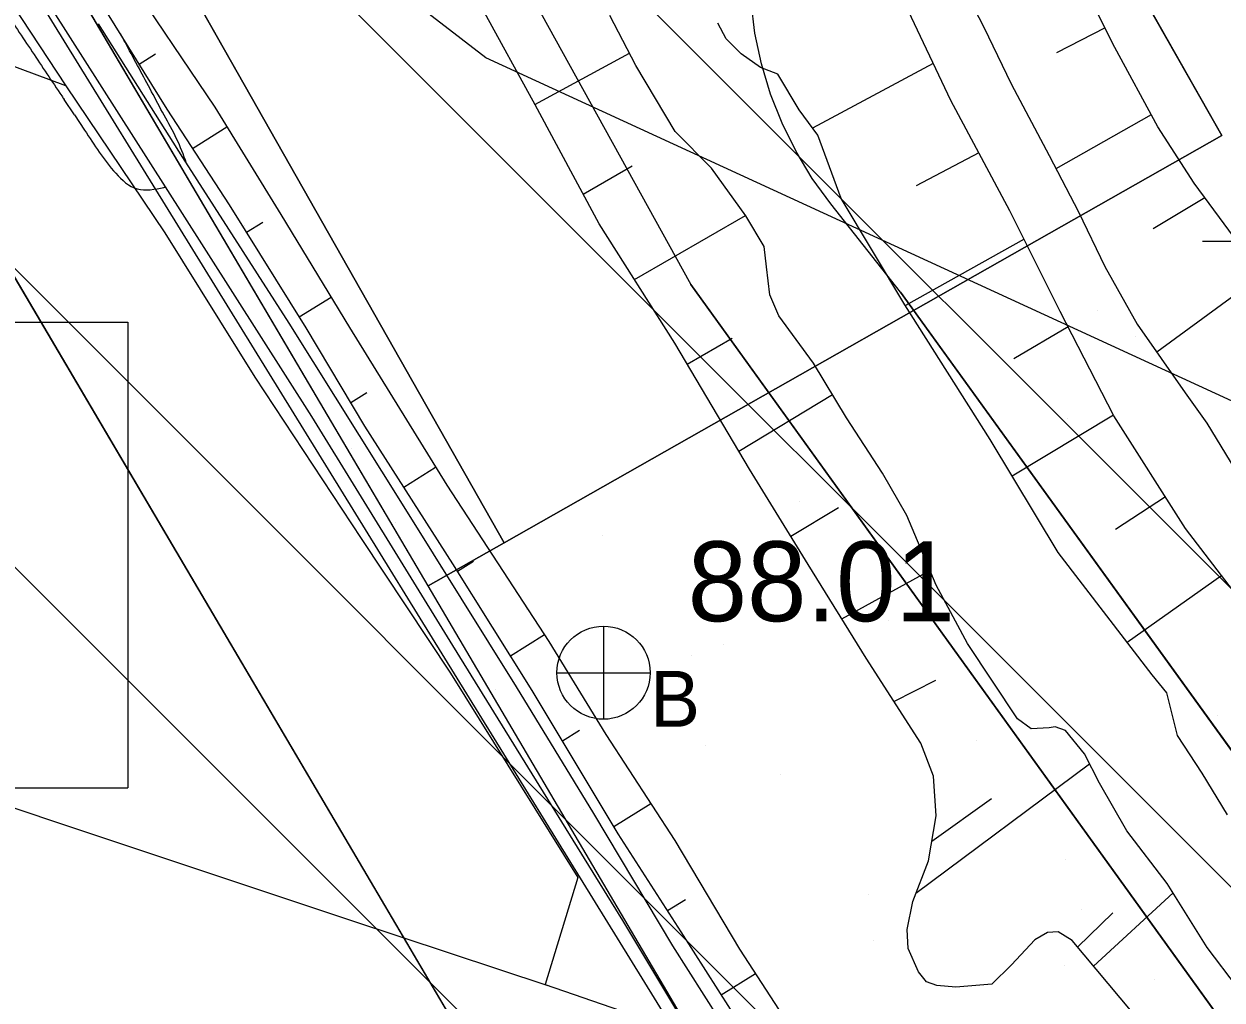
# Model space of a CAD drawing. Extents: x 417995 to 421451, y 4454518 to 4458015.
# Drawn here: x 420893.9 to 420983.9, y 4456249.9 to 4456323.2 of the extents above; entities that cross this region are included whole.
import ezdxf

# ---------------------------------------------------------------- set-up
doc = ezdxf.new("R2010")
doc.units = 0
for name, color, linetype in [('ADAKENARI', 7, 'Continuous'), ('Default', 7, 'Continuous'), ('Egri_1m', 7, 'Continuous'), ('Hid_Dere_Sulu_Yat_Gen', 7, 'Continuous'), ('PL_AYA_PARK_DINLENME', 7, 'Continuous'), ('PL_TA_K_DERE', 7, 'Continuous'), ('PL_TA_K_OTOPARK', 7, 'Continuous'), ('S_Rogar_Kapagi_Buski', 7, 'Continuous'), ('SEMBOL_FAT', 7, 'Continuous'), ('Sev_Sevalti', 7, 'Continuous'), ('Sev_Sevustu', 7, 'Continuous'), ('Sev_Tarama', 7, 'Continuous'), ('Sinir_itirazli_Mulkiyet', 7, 'Continuous'), ('Sinir_Tel_bir_taraf', 7, 'Continuous'), ('SN_TASKIN', 7, 'Continuous'), ('SN_TR_SIVILASMA', 7, 'Continuous'), ('SN_TR_TASKIN', 7, 'Continuous'), ('TR_PARKALANI', 7, 'Continuous'), ('TRFAT_PARKALANI', 7, 'Continuous'), ('Y_Kot_Noktasi', 7, 'Continuous'), ('Yol_Toprak_Duz', 7, 'Continuous'), ('Yol_Toprak_Kesik', 7, 'Continuous')]:
    doc.layers.add(name, color=color, linetype=linetype)

# ---------------------------------------------------------------- blocks, each defined once
blk = doc.blocks.new('POINT_DISPLAY')
at = {"layer": 'Default'}
blk.add_line((0, 0), (0, 0), dxfattribs=at)

msp = doc.modelspace()

# ---------------------------------------------------------------- linework, layer by layer
at = {"layer": 'ADAKENARI'}
for p, q in [((420983.888, 4456314.841), (420905.427, 4456453.119)), ((420924.233, 4456280.992), (420830.138, 4456440.665)), ((420852.304, 4456421.109), (420929.964, 4456284.244)), ((420866.39, 4456349.603), (420927.08, 4456246.617)), ((420929.964, 4456284.244), (420983.888, 4456314.841)), ((421053.63, 4456151.536), (420943.982, 4456303.649)), ((420959.726, 4456303.082), (421038.213, 4456194.409)), ((420924.233, 4456280.992), (420929.964, 4456284.244)), ((420960.939, 4456218.704), (420924.233, 4456280.992))]:
    msp.add_line(p, q, dxfattribs=at)
at = {"layer": 'Egri_1m'}
for q in [(420896.883, 4456317.563), (420898.428, 4456315.254)]:
    msp.add_line((420897.657, 4456316.409), q, dxfattribs=at)
for points in [[(420869.103, 4456359.489), (420870.183, 4456357.805), (420871.263, 4456356.121), (420872.342, 4456354.438), (420873.421, 4456352.754), (420874.5, 4456351.07), (420875.616, 4456349.41), (420876.793, 4456347.793), (420877.987, 4456346.189), (420879.182, 4456344.585), (420880.35, 4456342.961), (420881.455, 4456341.294), (420882.546, 4456339.618), (420883.636, 4456337.941), (420884.725, 4456336.264), (420885.81, 4456334.583), (420886.894, 4456332.903), (420887.978, 4456331.222), (420889.053, 4456329.536), (420890.129, 4456327.849), (420891.21, 4456326.167), (420892.294, 4456324.486), (420893.38, 4456322.807), (420894.487, 4456321.141), (420895.597, 4456319.477), (420896.712, 4456317.817), (420896.883, 4456317.563)], [(420906.094, 4456312.755), (420905.344, 4456314.609), (420904.402, 4456316.373), (420903.458, 4456318.137), (420902.514, 4456319.9), (420901.57, 4456321.663), (420901.147, 4456322.453)], [(420898.428, 4456315.254), (420899.533, 4456313.587), (420900.762, 4456312.009), (420902.379, 4456310.831), (420904.375, 4456310.944), (420904.484, 4456310.966)]]:
    msp.add_spline(points, degree=3, dxfattribs=at)
at = {"layer": 'Hid_Dere_Sulu_Yat_Gen'}
for points in [[(420985.062, 4456250.81), (420982.785, 4456253.81), (420979.767, 4456258.638), (420976.75, 4456262.595), (420974.698, 4456266.18), (420973.568, 4456268.371), (420972.138, 4456270.12), (420971.368, 4456270.413), (420970.898, 4456270.332), (420969.556, 4456270.251), (420968.519, 4456271.015), (420964.769, 4456276.679), (420962.421, 4456281.063), (420960.203, 4456286.282), (420958.387, 4456289.473), (420955.677, 4456293.622), (420953.195, 4456297.746), (420950.588, 4456301.305), (420949.93, 4456302.881), (420949.671, 4456304.974), (420949.481, 4456306.5), (420948.123, 4456308.814), (420945.548, 4456312.395), (420942.811, 4456315.14), (420939.86, 4456320.108), (420937.908, 4456323.855)], [(420984.314, 4456263.798), (420982.419, 4456266.915), (420980.554, 4456269.748), (420979.762, 4456272.97), (420978.644, 4456274.313), (420971.575, 4456283.501), (420966.485, 4456291.995), (420960.072, 4456302.133), (420955.291, 4456310.117), (420953.517, 4456314.873), (420952.132, 4456316.785), (420950.527, 4456319.462), (420949.214, 4456319.969), (420947.753, 4456320.979), (420946.632, 4456322.104), (420946.024, 4456323.298)]]:
    msp.add_lwpolyline(points, dxfattribs=at)
at = {"layer": 'PL_AYA_PARK_DINLENME'}
msp.add_lwpolyline([(420398.451, 4456770.435), (420341.542, 4456780.97), (420343.747, 4456814.103), (420500.975, 4456742.521), (420572.513, 4456705.355), (420639.693, 4456661.01), (420701.864, 4456609.89), (420758.351, 4456552.552), (420808.535, 4456489.624), (420852.304, 4456421.109), (420929.964, 4456284.244), (420924.233, 4456280.992), (420830.138, 4456440.665), (420780.571, 4456521.605), (420657.58, 4456639.752), (420530.801, 4456712.428), (420483.239, 4456735.932), (420462.904, 4456746.949), (420444.362, 4456753.772)], close=True, dxfattribs=at)
for points in [[(420806.621, 4456538.493), (420839.115, 4456497.136), (420881.948, 4456423.286), (420925.715, 4456349.165), (420926.198, 4456348.307), (420926.647, 4456347.431), (420927.06, 4456346.537), (420927.436, 4456345.627), (420927.776, 4456344.702), (420928.078, 4456343.765), (420928.342, 4456342.816), (420928.568, 4456341.858), (420932.166, 4456325.065), (420943.982, 4456303.649), (421053.63, 4456151.536)], [(421036.852, 4456094.936), (420796.811, 4456484.246), (420794.892, 4456487.096), (420792.752, 4456489.784), (420790.403, 4456492.291), (420787.862, 4456494.603), (420785.143, 4456496.704), (420782.266, 4456498.581), (420779.247, 4456500.221), (420776.107, 4456501.615), (420767.72, 4456504.943), (420764.74, 4456506.197), (420761.814, 4456507.572), (420758.947, 4456509.066), (420756.143, 4456510.675), (420753.408, 4456512.399), (420750.746, 4456514.233), (420748.161, 4456516.174), (420745.657, 4456518.22)], [(421038.213, 4456194.409), (420959.726, 4456303.082), (420954.498, 4456309.704), (420953.111, 4456311.62), (420951.889, 4456313.645), (420950.841, 4456315.765), (420949.973, 4456317.965), (420949.291, 4456320.229), (420948.801, 4456322.543), (420948.505, 4456324.889)]]:
    msp.add_lwpolyline(points, dxfattribs=at)
at = {"layer": 'PL_TA_K_DERE'}
msp.add_lwpolyline([(420859.034, 4456525.74), (420905.427, 4456453.119), (420983.888, 4456314.841), (420929.964, 4456284.244), (420852.304, 4456421.109), (420808.535, 4456489.624), (420758.351, 4456552.552), (420701.864, 4456609.89), (420639.693, 4456661.01), (420572.513, 4456705.355), (420500.975, 4456742.521), (420343.747, 4456814.103), (420348.148, 4456880.222), (420452.948, 4456832.51), (420528.13, 4456798.281), (420603.968, 4456758.881), (420676.56, 4456710.964), (420743.751, 4456655.717), (420804.798, 4456593.749)], close=True, dxfattribs=at)
for points in [[(420806.621, 4456538.493), (420839.115, 4456497.136), (420881.948, 4456423.286), (420925.715, 4456349.165), (420926.198, 4456348.307), (420926.647, 4456347.431), (420927.06, 4456346.537), (420927.436, 4456345.627), (420927.776, 4456344.702), (420928.078, 4456343.765), (420928.342, 4456342.816), (420928.568, 4456341.858), (420932.166, 4456325.065), (420943.982, 4456303.649), (421053.63, 4456151.536)], [(421038.213, 4456194.409), (420959.726, 4456303.082), (420954.498, 4456309.704), (420953.111, 4456311.62), (420951.889, 4456313.645), (420950.841, 4456315.765), (420949.973, 4456317.965), (420949.291, 4456320.229), (420948.801, 4456322.543), (420948.505, 4456324.889)]]:
    msp.add_lwpolyline(points, dxfattribs=at)
at = {"layer": 'PL_TA_K_OTOPARK'}
msp.add_lwpolyline([(420866.39, 4456349.603), (420927.08, 4456246.617), (420873.373, 4456214.968), (420858.4, 4456215.862)], close=True, dxfattribs=at)
at = {"layer": 'S_Rogar_Kapagi_Buski'}
for p, q in [((420937.422, 4456277.975), (420937.422, 4456270.975)), ((420933.922, 4456274.475), (420940.922, 4456274.475))]:
    msp.add_line(p, q, dxfattribs=at)
msp.add_circle((420937.422, 4456274.475), 3.5, dxfattribs=at)
at = {"layer": 'SEMBOL_FAT'}
for p, q in [((420866.683, 4456300.817), (420901.683, 4456300.817)), ((420901.683, 4456300.817), (420901.683, 4456265.817)), ((420866.683, 4456265.817), (420901.683, 4456265.817))]:
    msp.add_line(p, q, dxfattribs=at)
at = {"layer": 'Sev_Sevalti'}
for points in [[(420963.344, 4456328.139), (420966.006, 4456322.987), (420968.058, 4456318.733), (420970.902, 4456313.34), (420973.106, 4456309.118), (420975.094, 4456304.996), (420977.515, 4456300.672), (420981.134, 4456295.508), (420982.762, 4456293.238), (420986.266, 4456287.478)], [(420901.283, 4456327.28), (420908.216, 4456316.985), (420913.165, 4456308.915), (420918.337, 4456300.42), (420925.643, 4456288.557), (420933.321, 4456276.83), (420937.586, 4456269.822), (420942.786, 4456261.858), (420947.647, 4456253.703), (420954.256, 4456243.531), (420958.528, 4456236.175), (420966.516, 4456224.032), (420971.38, 4456216.094), (420976.395, 4456208.155), (420981.526, 4456200.822), (420985.462, 4456194.458)], [(420985.062, 4456250.81), (420982.785, 4456253.81), (420979.767, 4456258.638), (420976.75, 4456262.595), (420974.698, 4456266.18), (420973.568, 4456268.371), (420972.138, 4456270.12), (420971.368, 4456270.413), (420970.898, 4456270.332), (420969.556, 4456270.251), (420968.519, 4456271.015), (420964.769, 4456276.679), (420962.421, 4456281.063), (420960.203, 4456286.282), (420958.387, 4456289.473), (420955.677, 4456293.622), (420953.195, 4456297.746), (420950.588, 4456301.305), (420949.93, 4456302.881), (420949.671, 4456304.974), (420949.481, 4456306.5), (420948.123, 4456308.814), (420945.548, 4456312.395), (420942.811, 4456315.14), (420939.86, 4456320.108), (420937.908, 4456323.855)], [(420984.314, 4456263.798), (420982.419, 4456266.915), (420980.554, 4456269.748), (420979.762, 4456272.97), (420978.644, 4456274.313), (420971.575, 4456283.501), (420966.485, 4456291.995), (420960.072, 4456302.133), (420955.291, 4456310.117), (420953.517, 4456314.873), (420952.132, 4456316.785), (420950.527, 4456319.462), (420949.214, 4456319.969), (420947.753, 4456320.979), (420946.632, 4456322.104), (420946.024, 4456323.298)]]:
    msp.add_lwpolyline(points, dxfattribs=at)
at = {"layer": 'Sev_Sevustu'}
for points in [[(420986.118, 4456186.285), (420983.682, 4456190.808), (420980.752, 4456195.814), (420978.422, 4456200.183), (420975.008, 4456205.64), (420972.252, 4456209.721), (420968.116, 4456215.74), (420961.903, 4456224.453), (420956.922, 4456232.534), (420953.108, 4456239.135), (420948.812, 4456246.285), (420943.251, 4456254.991), (420938.533, 4456262.373), (420932.061, 4456273.131), (420926.108, 4456282.644), (420919.49, 4456292.991), (420915.077, 4456300.392), (420909.305, 4456309.632), (420904.629, 4456316.819), (420899.007, 4456325.916)], [(420985.18, 4456306.681), (420981.805, 4456311.277), (420979.078, 4456315.496), (420975.849, 4456321.459), (420973.7, 4456325.768)], [(420978.045, 4456247.893), (420972.638, 4456254.344), (420971.591, 4456255.008), (420970.797, 4456254.942), (420969.844, 4456254.388), (420968.072, 4456252.507), (420966.598, 4456251.069), (420963.888, 4456250.829), (420962.476, 4456250.976), (420961.685, 4456251.235), (420961.085, 4456251.981), (420960.311, 4456253.739), (420960.24, 4456255.174), (420960.656, 4456257.287), (420961.844, 4456260.326), (420962.426, 4456263.709), (420962.221, 4456266.71), (420961.271, 4456269.176), (420957.161, 4456275.564), (420952.809, 4456282.605), (420948.393, 4456289.777), (420942.787, 4456299.242), (420937.088, 4456308.209), (420932.28, 4456317.144), (420928.342, 4456324.311)], [(420986.498, 4456278.358), (420981.158, 4456285.315), (420975.77, 4456293.784), (420971.747, 4456301.626), (420967.959, 4456309.194), (420963.516, 4456317.477), (420960.105, 4456324.659)]]:
    msp.add_lwpolyline(points, dxfattribs=at)
at = {"layer": 'Sev_Tarama'}
for p, q in [((420975.116, 4456322.929), (420971.472, 4456321.069)), ((420902.53, 4456320.215), (420903.76, 4456320.994)), ((420932.256, 4456317.187), (420939.371, 4456321.047)), ((420962.192, 4456320.264), (420953.131, 4456315.406)), ((420978.582, 4456316.412), (420971.417, 4456312.352)), ((420906.54, 4456313.882), (420909.124, 4456315.504)), ((420965.625, 4456313.546), (420960.92, 4456311.061)), ((420935.893, 4456310.429), (420939.564, 4456312.572)), ((420982.62, 4456310.166), (420978.733, 4456307.838)), ((420939.74, 4456304.036), (420948.102, 4456308.844)), ((420910.59, 4456307.576), (420911.821, 4456308.338)), ((420969.029, 4456307.056), (420960.117, 4456302.063)), ((420986.971, 4456304.421), (420978.992, 4456298.564)), ((420914.562, 4456301.217), (420916.955, 4456302.69)), ((420972.344, 4456300.461), (420968.254, 4456298.062)), ((420943.717, 4456297.672), (420947.098, 4456299.617)), ((420918.424, 4456294.779), (420919.647, 4456295.543)), ((420947.601, 4456291.113), (420954.623, 4456295.373)), ((420975.742, 4456293.839), (420968.128, 4456289.253)), ((420922.413, 4456288.421), (420924.796, 4456289.932)), ((420979.654, 4456287.68), (420975.889, 4456285.234)), ((420951.502, 4456284.727), (420955.071, 4456286.878)), ((420926.447, 4456282.102), (420927.659, 4456282.865)), ((420955.328, 4456278.529), (420961.952, 4456282.167)), ((420983.877, 4456281.773), (420976.777, 4456276.739)), ((420930.422, 4456275.751), (420932.987, 4456277.34)), ((420959.249, 4456272.318), (420962.398, 4456273.911)), ((420934.336, 4456269.351), (420935.619, 4456270.148)), ((420960.901, 4456257.913), (420973.948, 4456267.634)), ((420962.099, 4456261.808), (420966.578, 4456265.018)), ((420938.204, 4456262.921), (420940.965, 4456264.648)), ((420974.248, 4456252.424), (420980.216, 4456257.919)), ((420942.229, 4456256.59), (420943.574, 4456257.434)), ((420973.05, 4456253.853), (420975.696, 4456256.433)), ((420946.265, 4456250.272), (420948.835, 4456251.875))]:
    msp.add_line(p, q, dxfattribs=at)
at = {"layer": 'Sinir_itirazli_Mulkiyet'}
msp.add_lwpolyline([(420817.883, 4456288.328), (420856.599, 4456276.556), (420896.692, 4456263.115), (420918.418, 4456255.886), (420933.234, 4456250.976)], dxfattribs=at)
at = {"layer": 'Sinir_Tel_bir_taraf'}
for points in [[(420869.804, 4456359.886), (420897.011, 4456318.583), (420856.887, 4456333.537)], [(420897.011, 4456318.583), (420904.451, 4456307.523), (420911.22, 4456296.688), (420919.213, 4456284.557), (420925.924, 4456274.44), (420935.489, 4456259.074), (420933.036, 4456251.042), (420941.526, 4456248.118), (420951.069, 4456232.731), (420961.7, 4456215.527), (420972.264, 4456198.173), (420973.561, 4456191.878), (420974.54, 4456186.26), (420975.818, 4456186.551)]]:
    msp.add_lwpolyline(points, dxfattribs=at)
at = {"layer": 'SN_TASKIN'}
msp.add_lwpolyline([(421279.092, 4456215.61), (421195.311, 4456240.09), (421032.227, 4456272.975), (420928.588, 4456320.689), (420834.213, 4456393.35), (420746.644, 4456480.517), (420663.922, 4456586.466), (420574.108, 4456669.499), (420422.961, 4456744.082), (420282.113, 4456812.001), (420160.798, 4456835.053), (420091.41, 4456837.401), (419960.894, 4456961.809), (419854.401, 4457049.617), (419750.612, 4457217.328), (419705.667, 4457319.894), (419669.268, 4457550.581), (419656.393, 4457729.951), (419636.417, 4457793.064)], dxfattribs=at)
at = {"layer": 'SN_TR_SIVILASMA'}
for p, q in [((421276.725, 4455988.655), (419957.486, 4457307.895)), ((421276.493, 4455966.436), (419971.974, 4457270.956)), ((421276.03, 4455921.999), (420004.046, 4457193.982)), ((421275.798, 4455899.78), (420015.354, 4457160.224))]:
    msp.add_line(p, q, dxfattribs=at)
at = {"layer": 'SN_TR_TASKIN'}
msp.add_line((420982.431, 4456306.904), (421082.431, 4456306.904), dxfattribs=at)
at = {"layer": 'TRFAT_PARKALANI'}
for p, q in [((420908.714, 4456310.275), (420908.714, 4456310.275)), ((420910.475, 4456308.098), (420910.475, 4456308.098)), ((420918.511, 4456291.339), (420918.511, 4456291.339)), ((420921.774, 4456285.797), (420921.774, 4456285.797)), ((420924.168, 4456284.08), (420924.168, 4456284.08)), ((420925.171, 4456282.359), (420925.171, 4456282.359))]:
    msp.add_line(p, q, dxfattribs=at)
at = {"layer": 'Yol_Toprak_Duz'}
msp.add_lwpolyline([(420789.26, 4456492.92), (420795.421, 4456485.04), (420803.339, 4456475.168), (420810.328, 4456461.944), (420821.051, 4456443.06), (420829.121, 4456429.476), (420833.084, 4456423.054), (420843.525, 4456407.947), (420854.01, 4456391.04), (420864.727, 4456373.565), (420874.282, 4456358.902), (420883.443, 4456343.853), (420894.787, 4456326.22), (420905.746, 4456308.981), (420915.468, 4456293.731), (420926.08, 4456276.518), (420938.844, 4456255.853), (420947.832, 4456240.871), (420958.275, 4456224.138), (420967.604, 4456210.497), (420975.273, 4456197.937)], dxfattribs=at)
at = {"layer": 'Yol_Toprak_Kesik'}
msp.add_lwpolyline([(420986.806, 4456183.278), (420982.122, 4456191.979), (420977.961, 4456198.828), (420972.868, 4456206.927), (420967.512, 4456214.877), (420964.15, 4456219.425), (420960.24, 4456225.392), (420956.057, 4456232.296), (420952.517, 4456238.355), (420947.338, 4456246.531), (420942.628, 4456253.952), (420936.698, 4456263.896), (420930.892, 4456273.404), (420922.565, 4456286.734), (420913.789, 4456300.742), (420905.81, 4456313.198), (420899.468, 4456323.245)], dxfattribs=at)

# ---------------------------------------------------------------- block references
at = {"layer": 'TR_PARKALANI', "xscale": 0.1, "yscale": 0.10000000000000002}
for p in [(420974.569, 4456301.714), (420977.419, 4456299.726), (420972.259, 4456293.59), (420952.152, 4456287.374), (420937.38, 4456284.769), (420931.648, 4456279.227), (420956.578, 4456278.68), (420958.812, 4456278.394), (420946.42, 4456276.623), (420944.04, 4456275.789), (420929.268, 4456273.184), (420983.558, 4456271.289), (420965.473, 4456269.414), (420945.087, 4456269.038), (420950.701, 4456266.809), (420935.929, 4456264.205), (420972.133, 4456260.434), (420957.361, 4456257.829), (420942.947, 4456256.926), (420973.36, 4456256.641), (420942.589, 4456255.225), (420957.719, 4456254.322), (420972.031, 4456252.485), (420978.794, 4456251.454)]:
    msp.add_blockref('POINT_DISPLAY', p, dxfattribs=at)

# ---------------------------------------------------------------- texts
at = {"layer": 'S_Rogar_Kapagi_Buski'}
msp.add_text('B', height=4.2, dxfattribs=at).set_placement((420940.922, 4456270.41))
at = {"layer": 'Y_Kot_Noktasi'}
msp.add_text('88.01', height=6, dxfattribs=at).set_placement((420943.749, 4456278.343))

doc.saveas('drawing.dxf')
